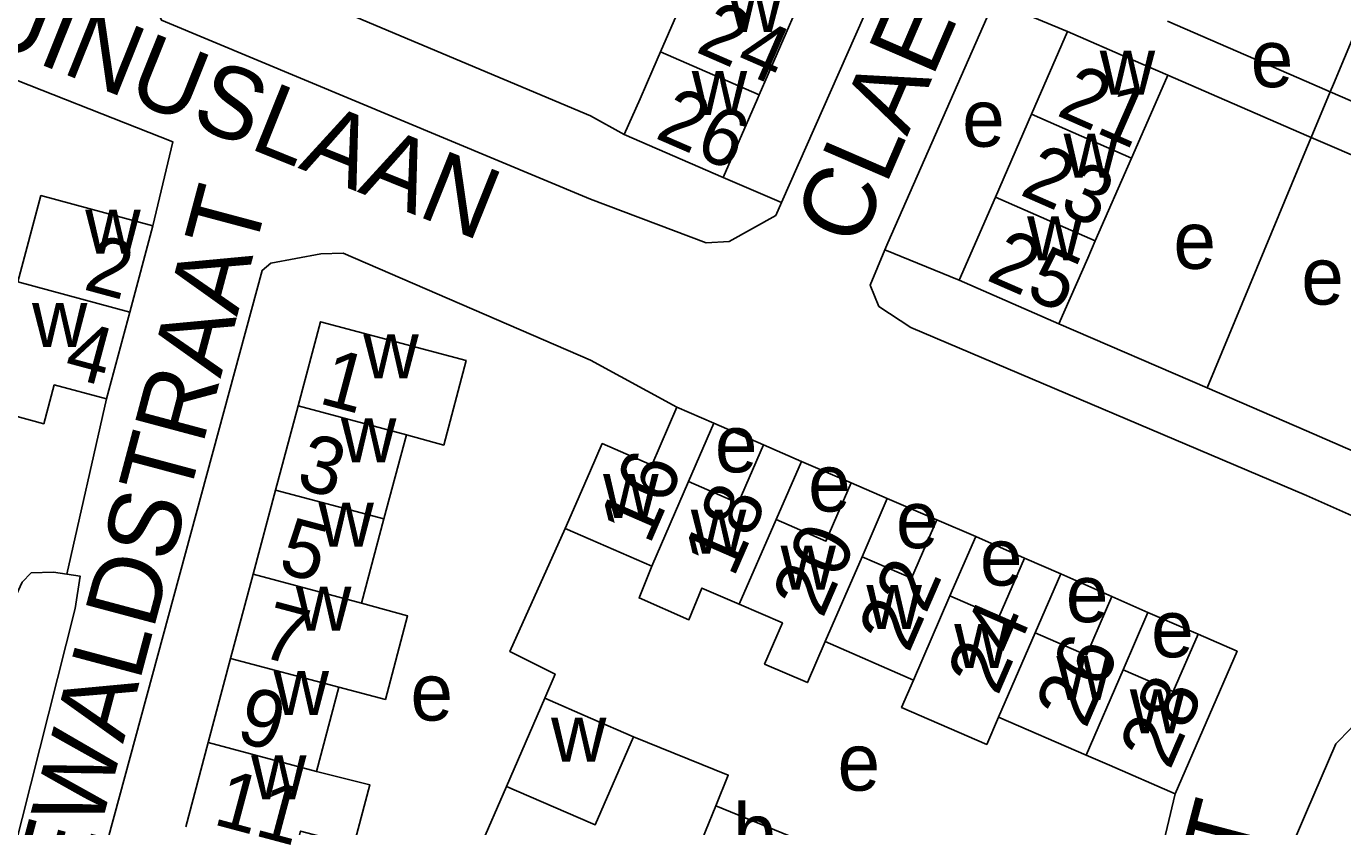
# Model space of a CAD drawing. Extents: x 162804 to 165059, y 381530 to 382901.
# Drawn here: x 163260.6 to 163352.5, y 381949.2 to 382005.1 of the extents above; entities that cross this region are included whole.
import ezdxf

# ---------------------------------------------------------------- set-up
doc = ezdxf.new("R2010")
doc.units = 0
for name, color, linetype in [('BLT_Basislijn', 7, 'Continuous'), ('BLT_Bebouwing', 7, 'Continuous'), ('BLT_Centroide', 7, 'Continuous'), ('BLT_Huisnummer', 7, 'Continuous'), ('BLT_Huisnummer_ tussenligend', 7, 'Continuous'), ('BLT_Onderverdeling_panden', 7, 'Continuous'), ('BLT_Straatnaam', 7, 'Continuous')]:
    doc.layers.add(name, color=color, linetype=linetype)

msp = doc.modelspace()

# ---------------------------------------------------------------- linework, layer by layer
at = {"layer": 'BLT_Basislijn'}
for p, q in [((163313.335, 381992.758), (163320.992, 382010.091)), ((163333.309, 382004.685), (163328.188, 382006.801)), ((163350, 382001.199), (163340.291, 382005.42)), ((163350, 381997.441), (163340.308, 382001.635)), ((163351.647, 382000.483), (163350, 382001.199)), ((163350.322, 381997.302), (163351.647, 382000.483)), ((163362.638, 381995.705), (163351.647, 382000.483)), ((163350.322, 381997.302), (163350, 381997.441)), ((163350, 381996.528), (163350.322, 381997.302)), ((163360.856, 381992.744), (163350.322, 381997.302)), ((163343.047, 381979.826), (163350, 381996.528)), ((163313.335, 381992.758), (163309.265, 381994.503)), ((163320.546, 381989.451), (163325.745, 381987.334)), ((163343.047, 381979.826), (163332.71, 381984.297)), ((163350, 381976.819), (163343.047, 381979.826)), ((163266.197, 381979.053), (163263.434, 381966.835)), ((163308.618, 381977.367), (163312.073, 381975.849)), ((163353.238, 381975.418), (163350, 381976.819)), ((163314.721, 381974.698), (163318.209, 381973.193)), ((163320.72, 381972.101), (163324.189, 381970.625)), ((163363.282, 381966.375), (163350, 381972.309)), ((163326.897, 381969.448), (163330.299, 381967.946)), ((163332.835, 381966.844), (163336.405, 381965.257)), ((163338.923, 381964.162), (163342.419, 381962.629))]:
    msp.add_line(p, q, dxfattribs=at)
for points in [[(163351.647, 382000.483), (163351.874, 382001.029), (163363.219, 382028.159)], [(163204.13, 382023.298), (163270.845, 381996.992), (163269.45, 381991.141)], [(163268.804, 382011.953), (163268.581, 382011.335), (163268.639, 382008.791), (163270.041, 382005.488), (163300, 381992.985), (163308.086, 381989.952), (163309.679, 381990.047), (163312.94, 381991.864), (163313.335, 381992.758)], [(163281.924, 382006.413), (163300, 381998.809), (163302.357, 381997.497)], [(163320.546, 381989.451), (163320.75, 381989.939), (163328.188, 382006.801)], [(163350, 381972.309), (163322.368, 381984.04), (163320.125, 381985.512), (163319.52, 381986.99), (163320.546, 381989.451)], [(163306.036, 381978.49), (163300, 381981.767), (163282.728, 381989.231), (163281.173, 381989.18), (163277.692, 381988.517), (163277.08, 381988.02), (163265.559, 381945.572), (163265.298, 381944.622)], [(163296.82, 381958.164), (163297.525, 381959.852), (163294.37, 381961.43), (163298.241, 381970.007)], [(163263.434, 381966.835), (163262.512, 381966.975), (163260.956, 381966.917), (163260.319, 381966.28), (163246.312, 381935.837)], [(163263.434, 381966.835), (163264.367, 381966.694), (163264.016, 381964.437), (163257.208, 381937.514), (163255.952, 381935.359), (163255.346, 381934.849), (163252.413, 381933.688), (163249.347, 381934.09), (163248.429, 381934.434), (163246.312, 381935.837)], [(163350, 381950.244), (163352.039, 381954.98), (163353.09, 381956.069), (163354.587, 381956.955), (163357.613, 381956.859), (163370.933, 381950.319)], [(163302.999, 381955.478), (163309.614, 381952.81), (163308.747, 381950.655)], [(163277.734, 381941.306), (163288.222, 381938.463), (163288.605, 381938.845), (163289.726, 381941.906), (163294.145, 381952.011)], [(163337.944, 381939.429), (163338.248, 381940.641), (163340.821, 381951.498)], [(163335.808, 381899.23), (163348.09, 381945.807), (163350, 381950.244)]]:
    msp.add_lwpolyline(points, dxfattribs=at)
at = {"layer": 'BLT_Bebouwing'}
for p, q in [((163304.886, 382003.271), (163307.394, 382009.044)), ((163311.783, 382000.271), (163314.29, 382006.044)), ((163331.267, 382000), (163333.309, 382004.685)), ((163340.308, 382001.635), (163339.596, 382000)), ((163302.357, 381997.497), (163303.465, 382000)), ((163311.665, 382000), (163309.265, 381994.503)), ((163311.665, 382000), (163311.783, 382000.271)), ((163331.267, 382000), (163330.795, 381998.916)), ((163337.779, 381995.856), (163339.596, 382000)), ((163330.795, 381998.916), (163328.273, 381993.132)), ((163309.265, 381994.503), (163302.357, 381997.497)), ((163335.244, 381990.077), (163337.779, 381995.856)), ((163328.273, 381993.132), (163325.745, 381987.334)), ((163269.45, 381991.141), (163267.827, 381985.111)), ((163325.745, 381987.334), (163332.71, 381984.297)), ((163267.827, 381985.111), (163266.197, 381979.053)), ((163279.58, 381978.574), (163278.012, 381972.699)), ((163306.036, 381978.49), (163308.618, 381977.367)), ((163285.574, 381970.681), (163287.142, 381976.556)), ((163308.618, 381977.367), (163306.845, 381973.289)), ((163312.073, 381975.849), (163314.721, 381974.698)), ((163314.721, 381974.698), (163312.955, 381970.637)), ((163318.209, 381973.193), (163320.72, 381972.101)), ((163278.012, 381972.699), (163276.444, 381966.824)), ((163320.72, 381972.101), (163318.958, 381968.045)), ((163284.006, 381964.806), (163285.574, 381970.681)), ((163324.189, 381970.625), (163326.897, 381969.448)), ((163326.897, 381969.448), (163325.099, 381965.314)), ((163330.299, 381967.946), (163332.835, 381966.844)), ((163276.444, 381966.824), (163274.876, 381960.949)), ((163332.835, 381966.844), (163331.046, 381962.73)), ((163336.405, 381965.257), (163338.923, 381964.162)), ((163338.923, 381964.162), (163337.184, 381960.161)), ((163322.547, 381959.441), (163316.384, 381962.12)), ((163274.876, 381960.949), (163273.308, 381955.074)), ((163280.87, 381953.056), (163282.438, 381958.931)), ((163296.82, 381958.164), (163294.145, 381952.011)), ((163334.596, 381954.204), (163328.494, 381956.856)), ((163273.308, 381955.074), (163271.74, 381949.199)), ((163308.747, 381950.655), (163307.195, 381946.864)), ((163314.886, 381948.141), (163308.747, 381950.655))]:
    msp.add_line(p, q, dxfattribs=at)
for points in [[(163333.309, 382004.685), (163337.893, 382002.688), (163340.308, 382001.635)], [(163304.886, 382003.271), (163304.352, 382002.041), (163303.465, 382000)], [(163260.009, 381987.215), (163261.632, 381993.245), (163269.45, 381991.141)], [(163332.71, 381984.297), (163334.718, 381988.877), (163335.244, 381990.077)], [(163266.197, 381979.053), (163262.56, 381980.032), (163261.832, 381977.326), (163256.377, 381978.794), (163256.519, 381979.319), (163254.111, 381979.967), (163254.974, 381983.173), (163255.565, 381983.014), (163256.919, 381988.046), (163260.009, 381987.215)], [(163287.142, 381976.556), (163289.751, 381975.838), (163291.318, 381981.729), (163281.147, 381984.444), (163279.58, 381978.574)], [(163298.241, 381970.007), (163298.824, 381971.348), (163300, 381974.055), (163300.821, 381975.943), (163304.276, 381974.441), (163306.036, 381978.49)], [(163306.845, 381973.289), (163310.306, 381971.785), (163312.073, 381975.849)], [(163312.955, 381970.637), (163316.439, 381969.122), (163318.209, 381973.193)], [(163318.958, 381968.045), (163322.415, 381966.543), (163324.189, 381970.625)], [(163304.279, 381967.382), (163300, 381969.242), (163298.241, 381970.007)], [(163310.387, 381964.727), (163307.779, 381965.861), (163306.866, 381963.652), (163303.388, 381965.164), (163304.279, 381967.382)], [(163325.099, 381965.314), (163328.51, 381963.831), (163330.299, 381967.946)], [(163282.438, 381958.931), (163285.677, 381958.086), (163287.234, 381963.919), (163284.006, 381964.806)], [(163316.384, 381962.12), (163315.144, 381959.258), (163312.152, 381960.558), (163313.396, 381963.42), (163310.387, 381964.727)], [(163331.046, 381962.73), (163334.629, 381961.172), (163336.405, 381965.257)], [(163337.184, 381960.161), (163340.685, 381958.639), (163342.419, 381962.629)], [(163342.419, 381962.629), (163345.145, 381961.444), (163340.821, 381951.498)], [(163328.494, 381956.856), (163327.66, 381954.948), (163321.719, 381957.526), (163322.547, 381959.441)], [(163302.999, 381955.478), (163300, 381956.781), (163296.82, 381958.164)], [(163294.145, 381952.011), (163300, 381949.466), (163300.324, 381949.325), (163302.999, 381955.478)], [(163340.821, 381951.498), (163336.236, 381953.491), (163334.596, 381954.204)], [(163279.302, 381947.181), (163279.761, 381948.9), (163283.473, 381947.909), (163284.598, 381952.125), (163280.87, 381953.056)]]:
    msp.add_lwpolyline(points, dxfattribs=at)
at = {"layer": 'BLT_Onderverdeling_panden'}
for p, q in [((163311.783, 382000.271), (163304.886, 382003.271)), ((163337.779, 381995.856), (163330.795, 381998.916)), ((163335.244, 381990.077), (163328.273, 381993.132)), ((163260.009, 381987.215), (163267.827, 381985.111)), ((163287.142, 381976.556), (163279.58, 381978.574)), ((163306.845, 381973.289), (163304.279, 381967.382)), ((163285.574, 381970.681), (163278.012, 381972.699)), ((163312.955, 381970.637), (163310.387, 381964.727)), ((163318.958, 381968.045), (163316.384, 381962.12)), ((163284.006, 381964.806), (163276.444, 381966.824)), ((163325.099, 381965.314), (163322.547, 381959.441)), ((163331.046, 381962.73), (163328.494, 381956.856)), ((163282.438, 381958.931), (163274.876, 381960.949)), ((163337.184, 381960.161), (163334.596, 381954.204)), ((163280.87, 381953.056), (163273.308, 381955.074))]:
    msp.add_line(p, q, dxfattribs=at)

# ---------------------------------------------------------------- texts
at = {"layer": 'BLT_Centroide'}
for s, p in [('w', (163309.586, 382004.656)), ('w', (163335.555, 382000.281)), ('e', (163346.096, 382000.808)), ('w', (163307.07, 381998.875)), ('e', (163325.952, 381996.652)), ('w', (163333.031, 381994.5)), ('w', (163264.727, 381989.188)), ('w', (163330.492, 381988.719)), ('e', (163340.696, 381988.132)), ('e', (163349.626, 381985.639)), ('w', (163261.008, 381982.688)), ('w', (163284.141, 381980.5)), ('w', (163282.578, 381974.625)), ('e', (163308.685, 381973.932)), ('w', (163300.882, 381970.744)), ('e', (163315.196, 381971.197)), ('w', (163281.008, 381968.75)), ('w', (163307.01, 381968.248)), ('e', (163321.325, 381968.642)), ('w', (163313.27, 381965.753)), ('e', (163327.191, 381966.032)), ('e', (163333.188, 381963.477)), ('w', (163279.438, 381962.875)), ('w', (163319.267, 381962.995)), ('e', (163339.141, 381961.026)), ('w', (163325.396, 381960.281)), ('w', (163332.531, 381958.049)), ('w', (163277.875, 381957)), ('e', (163287.429, 381956.613)), ('w', (163337.653, 381955.729)), ('w', (163297.245, 381953.75)), ('e', (163317.248, 381951.721)), ('w', (163276.305, 381951.125)), ('b', (163309.969, 381946.832))]:
    msp.add_text(s, height=4, dxfattribs=at).set_placement(p)
at = {"layer": 'BLT_Huisnummer'}
for s, rotation, p in [('21', 336.33748, (163332.439, 381998.885)), ('26', 336.56758, (163304.411, 381997.296)), ('2', 344.93729, (163264.504, 381986.723)), ('25', 336.441, (163327.536, 381987.387)), ('4', 344.93792, (163263.111, 381980.711)), ('1', 345.05821, (163280.927, 381978.778)), ('16', 66.51988, (163304.117, 381968.787)), ('5', 345.05821, (163278.091, 381966.993)), ('20', 66.51841, (163316.206, 381963.666)), ('24', 66.51713, (163328.427, 381958.259)), ('28', 66.50312, (163340.447, 381953.086)), ('9', 345.05821, (163275.138, 381955.194))]:
    msp.add_text(s, height=4, rotation=rotation, dxfattribs=at).set_placement(p)
at = {"layer": 'BLT_Huisnummer_ tussenligend'}
for s, rotation, p in [('24', 336.48715, (163307.251, 382003.302)), ('23', 336.33748, (163329.88, 381993.338)), ('3', 345.05821, (163279.347, 381972.879)), ('18', 66.51988, (163309.987, 381966.504)), ('22', 66.51841, (163322.221, 381961.244)), ('7', 345.05821, (163276.789, 381961.124)), ('26', 66.51713, (163334.581, 381955.969)), ('11', 345.05821, (163273.559, 381949.4))]:
    msp.add_text(s, height=4, rotation=rotation, dxfattribs=at).set_placement(p)
at = {"layer": 'BLT_Straatnaam'}
for s, rotation, p in [('CLAES BERCHEMSTRAAT', 66.62033, (163318.706, 381989.474)), ('ST LEBUINUSLAAN', 338.10403, (163235.395, 382012.925)), ('ST EWALDSTRAAT', 75.05444, (163261.901, 381934.5)), ('ST WILFRIEDSTRAAT', 75.26341, (163329.637, 381883.684))]:
    msp.add_text(s, height=5, rotation=rotation, dxfattribs=at).set_placement(p)

doc.saveas('drawing.dxf')
